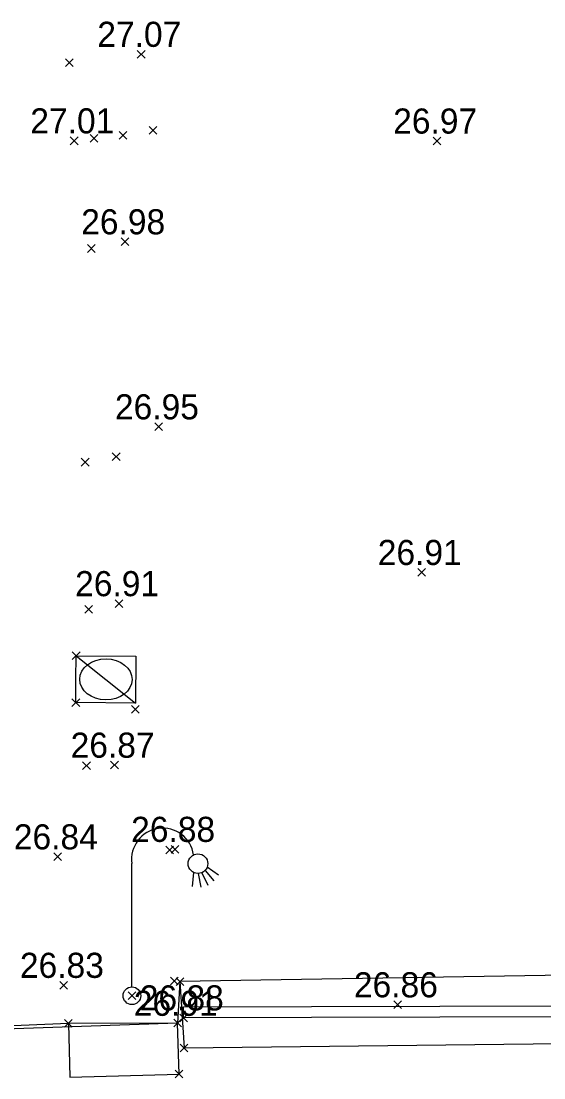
# Model space of a CAD drawing. Extents: x 37864 to 38032, y 453991 to 454052.
# Drawn here: x 37888.14 to 37894.08, y 454004.08 to 454016.08 of the extents above; entities that cross this region are included whole.
import ezdxf

# ---------------------------------------------------------------- set-up
doc = ezdxf.new("R2010")
doc.units = 0
for name, color, linetype in [('DH_CALCUL SURFACE-TEXTE', 7, 'Continuous'), ('GO_POTEAU', 7, 'Continuous'), ('PS_Bolt', 7, 'Continuous'), ('PS_Dim', 7, 'Continuous'), ('PS_Mid', 7, 'Continuous'), ('PS_Object', 7, 'Continuous'), ('PS_RoofWall', 7, 'Continuous'), ('SO_MENUISERIE EXT DOR', 7, 'Continuous')]:
    doc.layers.add(name, color=color, linetype=linetype)

# ---------------------------------------------------------------- blocks, each defined once
blk = doc.blocks.new('A-REGARD')
for p, q in [((0, 1), (1, 1)), ((0, 0), (1, 1)), ((0, 0), (0, 1)), ((1, 1), (1, 0)), ((0.5, 0), (0, 0)), ((1, 0), (0.5, 0))]:
    blk.add_line(p, q)
blk.add_circle((0.5, 0.5), 0.438)
blk = doc.blocks.new('V-EP-CANDELAB')
for p, q in [((0, 0.1), (0, 1.5)), ((0.855244, 1.462269), (0.984837, 1.372556)), ((0.700628, 1.399688), (0.684459, 1.240974)), ((0.752708, 1.388229), (0.78082, 1.234594)), ((0.792944, 1.396773), (0.86024, 1.256612)), ((0.830421, 1.422331), (0.931041, 1.303495))]:
    blk.add_line(p, q)
for centre, radius in [((0.75, 1.5), 0.111803), ((0, 0), 0.1)]:
    blk.add_circle(centre, radius)
blk.add_arc((0.35, 1.55), 0.353553, 8.130102, 188.130102)
blk = doc.blocks.new('POINT_DISPLAY')
for p, q in [((-0.04375, -0.04375), (0.04375, 0.04375)), ((-0.04375, 0.04375), (0.04375, -0.04375))]:
    blk.add_line(p, q)
blk = doc.blocks.new('POINTCOT')
blk.add_blockref('POINT_DISPLAY', (0, 0))

msp = doc.modelspace()

# ---------------------------------------------------------------- linework, layer by layer
at = {"layer": 'PS_Bolt'}
msp.add_lwpolyline([(37889.933, 454004.128), (37889.917, 454004.706), (37888.676, 454004.703), (37888.694, 454004.093), (37889.933, 454004.128)], dxfattribs=at)
at = {"layer": 'PS_Dim'}
for p, q in [((37896.018, 454004.902), (37889.985, 454004.888)), ((37889.985, 454004.766), (37889.985, 454004.888)), ((37896.018, 454004.78), (37889.985, 454004.766)), ((37888.676, 454004.703), (37883.591, 454004.486))]:
    msp.add_line(p, q, dxfattribs=at)
at = {"layer": 'PS_Mid'}
msp.add_lwpolyline([(37895.934, 454004.494), (37902.003, 454004.482), (37902.037, 454005.008), (37902.272, 454004.945), (37902.939, 454004.305), (37903.058, 454004.44), (37902.422, 454005.291), (37895.242, 454005.264), (37889.943, 454005.178), (37889.991, 454004.425), (37895.934, 454004.494)], dxfattribs=at)
at = {"layer": 'PS_Object'}
msp.add_lwpolyline([(37895.242, 454005.264), (37889.943, 454005.178), (37889.917, 454004.706), (37883.591, 454004.486), (37882.985, 454004.477), (37882.985, 454030.398)], dxfattribs=at)

# ---------------------------------------------------------------- block references
at = {"layer": 'DH_CALCUL SURFACE-TEXTE', "rotation": 2.2526485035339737e-05}
for p in [(37889.503, 454015.708), (37888.687, 454015.614), (37889.637, 454014.843), (37888.742, 454014.725), (37888.967, 454014.754), (37889.298, 454014.788), (37892.863, 454014.723), (37888.936, 454013.502), (37889.32, 454013.579), (37889.703, 454011.478), (37889.219, 454011.139), (37888.867, 454011.076), (37892.688, 454009.825), (37888.908, 454009.406), (37889.251, 454009.47), (37888.765, 454008.878), (37888.761, 454008.346), (37889.436, 454008.268), (37888.882, 454007.631), (37889.2, 454007.636), (37889.826, 454006.672), (37889.887, 454006.68), (37888.555, 454006.595), (37888.624, 454005.136), (37889.879, 454005.185), (37889.943, 454005.178), (37889.398, 454005.017), (37892.417, 454004.916), (37889.985, 454004.766), (37888.676, 454004.703), (37889.917, 454004.706), (37889.991, 454004.425), (37889.933, 454004.128)]:
    msp.add_blockref('POINTCOT', p, dxfattribs=at)
at = {"layer": 'PS_RoofWall', "rotation": 2.2526485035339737e-05}
msp.add_blockref('V-EP-CANDELAB', (37889.398, 454005.017), dxfattribs=at)
at = {"layer": 'SO_MENUISERIE EXT DOR', "xscale": 0.532415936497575, "yscale": 0.6790135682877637, "rotation": -90.4496288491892}
msp.add_blockref('A-REGARD', (37888.765, 454008.878), dxfattribs=at)

# ---------------------------------------------------------------- texts
at = {"layer": 'GO_POTEAU'}
for s, p in [('27.07', (37889.005, 454015.792)), ('27.01', (37888.244, 454014.809)), ('26.97', (37892.365, 454014.807)), ('26.98', (37888.822, 454013.663)), ('26.95', (37889.205, 454011.562)), ('26.91', (37892.19, 454009.908)), ('26.91', (37888.753, 454009.554)), ('26.87', (37888.702, 454007.72)), ('26.88', (37889.389, 454006.764)), ('26.84', (37888.057, 454006.679)), ('26.83', (37888.126, 454005.22)), ('26.86', (37891.919, 454004.999)), ('26.88', (37889.487, 454004.85)), ('26.91', (37889.419, 454004.789))]:
    msp.add_text(s, height=0.285, rotation=0, dxfattribs=at).set_placement(p)

doc.saveas('drawing.dxf')
